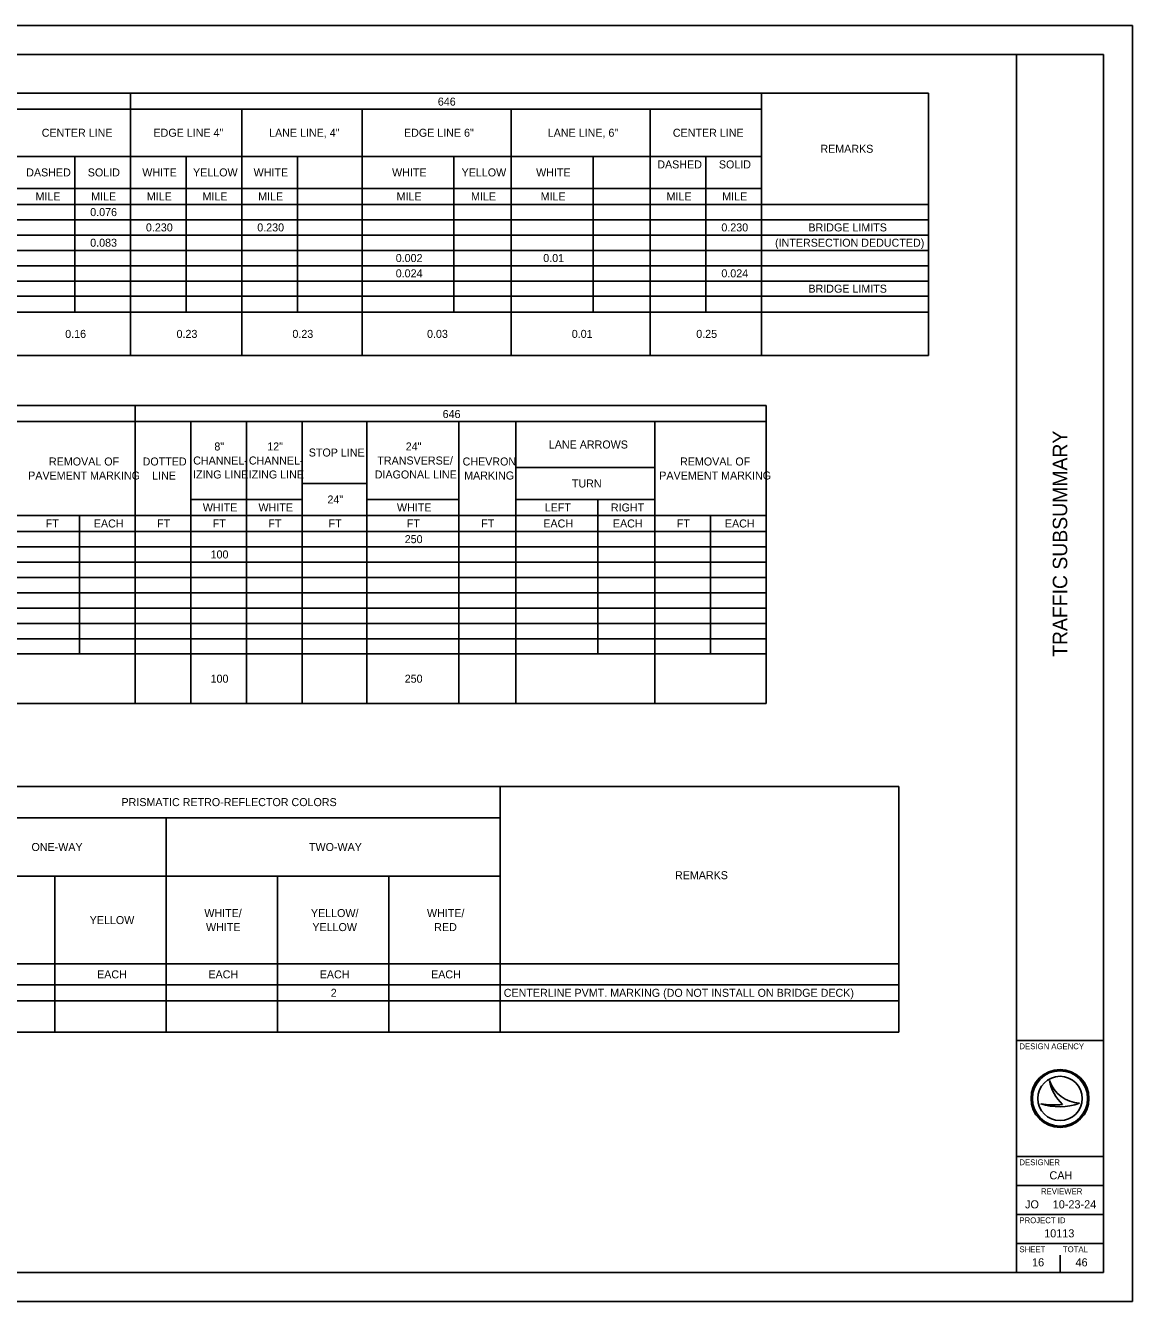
# Model space of a CAD drawing. Extents: x 0 to 53.1, y -5.3 to 22.
# Drawn here: x 14.91 to 34, y 0 to 22 of the extents above; entities that cross this region are included whole.
import ezdxf

# ---------------------------------------------------------------- set-up
doc = ezdxf.new("R2010")
doc.units = 0
for name, color, linetype in [('SH_Border', 7, 'Continuous'), ('SH_Cut_Line', 7, 'Continuous'), ('SH_Data', 7, 'Continuous'), ('SH_Text', 7, 'Continuous')]:
    doc.layers.add(name, color=color, linetype=linetype)

msp = doc.modelspace()

# ---------------------------------------------------------------- linework, layer by layer
at = {"layer": 'SH_Border'}
for p, q in [((32, 0.5), (32, 21.5)), ((32, 4.5), (33.5, 4.5)), ((32, 2.5), (33.5, 2.5)), ((32, 2), (33.5, 2)), ((32, 1.5), (33.5, 1.5)), ((32, 1), (33.5, 1))]:
    msp.add_line(p, q, dxfattribs=at)
msp.add_lwpolyline([(1.5, 21.5), (33.5, 21.5), (33.5, 0.5), (1.5, 0.5)], close=True, dxfattribs=at)
at = {"layer": 'SH_Cut_Line'}
msp.add_lwpolyline([(0, 0), (34, 0), (34, 22), (0, 22)], close=True, dxfattribs=at)
at = {"layer": 'SH_Data'}
for p, q in [((32.567, 3.81), (32.567, 3.81)), ((32.417, 3.41), (32.417, 3.41)), ((32.75, 3.5), (32.75, 3.5)), ((33.087, 3.419), (33.087, 3.419)), ((32.375, 0.675), (32.375, 0.675)), ((32.75, 0.5), (32.75, 0.8))]:
    msp.add_line(p, q, dxfattribs=at)
for radius in [0.5, 0.477, 0.477, 0.382]:
    msp.add_circle((32.75, 3.5), radius, dxfattribs=at)
for centre, radius, start, end in [((33.116, 3.998), 0.58, 198.9257, 198.9319), ((33.347, 3.97), 0.796, 191.6379, 191.6421), ((33.116, 3.998), 0.58, 198.9319, 267.1657), ((33.347, 3.97), 0.796, 191.6421, 226.0947), ((32.739, 4.37), 1.013, 251.4576, 290.0832), ((32.648, 4.654), 1.266, 259.4964, 259.4995), ((32.739, 4.37), 1.013, 251.4527, 251.4576), ((32.648, 4.654), 1.266, 259.4995, 276.6672)]:
    msp.add_arc(centre, radius, start, end, dxfattribs=at)
at = {"layer": 'SH_Text'}
for p, q in [((7.85, 20.835), (30.482, 20.835)), ((16.718, 20.835), (16.718, 20.559)), ((27.602, 20.835), (27.602, 20.019)), ((30.482, 20.835), (30.482, 20.019)), ((10.034, 20.559), (27.602, 20.559)), ((16.718, 20.559), (16.718, 20.019)), ((18.638, 20.559), (18.638, 20.019)), ((20.714, 20.559), (20.714, 20.019)), ((23.282, 20.559), (23.282, 20.019)), ((25.682, 20.559), (25.682, 20.019)), ((16.718, 20.019), (16.718, 19.467)), ((18.638, 20.019), (18.638, 19.743)), ((20.714, 20.019), (20.714, 19.467)), ((23.282, 20.019), (23.282, 19.743)), ((25.682, 20.019), (25.682, 19.467)), ((27.602, 20.019), (27.602, 19.467)), ((30.482, 20.019), (30.482, 19.467)), ((10.034, 19.743), (27.602, 19.743)), ((15.758, 19.743), (15.758, 19.467)), ((17.678, 19.743), (17.678, 19.467)), ((18.638, 19.743), (18.638, 19.467)), ((19.598, 19.743), (19.598, 19.467)), ((22.298, 19.743), (22.298, 19.467)), ((23.282, 19.743), (23.282, 19.467)), ((24.698, 19.743), (24.698, 19.467)), ((26.642, 19.743), (26.642, 19.467)), ((15.758, 19.467), (15.758, 19.191)), ((16.718, 19.467), (16.718, 19.191)), ((17.678, 19.467), (17.678, 19.191)), ((18.638, 19.467), (18.638, 19.191)), ((19.598, 19.467), (19.598, 19.191)), ((20.714, 19.467), (20.714, 19.191)), ((22.298, 19.467), (22.298, 19.191)), ((23.282, 19.467), (23.282, 19.191)), ((24.698, 19.467), (24.698, 19.191)), ((25.682, 19.467), (25.682, 19.191)), ((26.642, 19.467), (26.642, 19.191)), ((27.602, 19.467), (27.602, 19.191)), ((30.482, 19.467), (30.482, 19.191)), ((7.85, 19.191), (27.602, 19.191)), ((15.758, 19.191), (15.758, 17.859)), ((16.718, 19.191), (16.718, 17.859)), ((17.678, 19.191), (17.678, 17.859)), ((18.638, 19.191), (18.638, 17.859)), ((19.598, 19.191), (19.598, 17.859)), ((20.714, 19.191), (20.714, 17.859)), ((22.298, 19.191), (22.298, 17.859)), ((23.282, 19.191), (23.282, 17.859)), ((24.698, 19.191), (24.698, 17.859)), ((25.682, 19.191), (25.682, 17.859)), ((26.642, 19.191), (26.642, 17.859)), ((27.602, 19.191), (27.602, 17.859)), ((30.482, 19.191), (30.482, 17.859)), ((7.85, 18.915), (30.482, 18.915)), ((7.85, 18.651), (30.482, 18.651)), ((7.85, 18.387), (30.482, 18.387)), ((7.85, 18.123), (30.482, 18.123)), ((7.85, 17.859), (30.482, 17.859)), ((15.758, 17.859), (15.758, 17.595)), ((16.718, 17.859), (16.718, 17.595)), ((17.678, 17.859), (17.678, 17.595)), ((18.638, 17.859), (18.638, 17.595)), ((19.598, 17.859), (19.598, 17.595)), ((20.714, 17.859), (20.714, 17.595)), ((22.298, 17.859), (22.298, 17.595)), ((23.282, 17.859), (23.282, 17.595)), ((24.698, 17.859), (24.698, 17.595)), ((25.682, 17.859), (25.682, 17.595)), ((26.642, 17.859), (26.642, 17.595)), ((27.602, 17.859), (27.602, 17.595)), ((30.482, 17.859), (30.482, 17.595)), ((7.85, 17.595), (30.482, 17.595)), ((15.758, 17.595), (15.758, 17.055)), ((16.718, 17.595), (16.718, 16.311)), ((17.678, 17.595), (17.678, 17.055)), ((18.638, 17.595), (18.638, 16.311)), ((19.598, 17.595), (19.598, 17.055)), ((20.714, 17.595), (20.714, 16.311)), ((22.298, 17.595), (22.298, 17.055)), ((23.282, 17.595), (23.282, 16.311)), ((24.698, 17.595), (24.698, 17.055)), ((25.682, 17.595), (25.682, 16.311)), ((26.642, 17.595), (26.642, 17.055)), ((27.602, 17.595), (27.602, 16.311)), ((30.482, 17.595), (30.482, 16.311)), ((7.85, 17.331), (30.482, 17.331)), ((7.85, 17.055), (30.482, 17.055)), ((7.85, 16.311), (30.482, 16.311)), ((7.933, 15.448), (27.685, 15.448)), ((16.801, 15.448), (16.801, 15.172)), ((27.685, 15.448), (27.685, 15.172)), ((7.933, 15.172), (27.685, 15.172)), ((16.801, 15.172), (16.801, 14.656)), ((17.761, 15.172), (17.761, 14.656)), ((18.721, 15.172), (18.721, 14.656)), ((19.681, 15.172), (19.681, 14.656)), ((20.797, 15.172), (20.797, 14.656)), ((22.381, 15.172), (22.381, 14.656)), ((23.365, 15.172), (23.365, 14.656)), ((25.765, 15.172), (25.765, 14.656)), ((27.685, 15.172), (27.685, 14.656)), ((16.801, 14.656), (16.801, 14.38)), ((17.761, 14.656), (17.761, 14.38)), ((18.721, 14.656), (18.721, 14.38)), ((19.681, 14.656), (19.681, 14.38)), ((20.797, 14.656), (20.797, 14.38)), ((22.381, 14.656), (22.381, 14.38)), ((23.365, 14.656), (23.365, 14.38)), ((25.765, 14.656), (25.765, 14.38)), ((27.685, 14.656), (27.685, 14.38)), ((16.801, 14.38), (16.801, 14.104)), ((17.761, 14.38), (17.761, 14.104)), ((18.721, 14.38), (18.721, 14.104)), ((19.681, 14.38), (19.681, 14.104)), ((20.797, 14.38), (20.797, 14.104)), ((22.381, 14.38), (22.381, 14.104)), ((23.365, 14.38), (25.765, 14.38)), ((23.365, 14.38), (23.365, 14.104)), ((25.765, 14.38), (25.765, 14.104)), ((27.685, 14.38), (27.685, 14.104)), ((16.801, 14.104), (16.801, 13.828)), ((17.761, 14.104), (17.761, 13.828)), ((18.721, 14.104), (18.721, 13.828)), ((19.681, 14.104), (20.797, 14.104)), ((19.681, 14.104), (19.681, 13.828)), ((20.797, 14.104), (20.797, 13.828)), ((22.381, 14.104), (22.381, 13.828)), ((23.365, 14.104), (23.365, 13.828)), ((25.765, 14.104), (25.765, 13.828)), ((27.685, 14.104), (27.685, 13.828)), ((16.801, 13.828), (16.801, 13.552)), ((17.761, 13.828), (19.681, 13.828)), ((17.761, 13.828), (17.761, 13.552)), ((18.721, 13.828), (18.721, 13.552)), ((19.681, 13.828), (19.681, 13.552)), ((20.797, 13.828), (22.381, 13.828)), ((20.797, 13.828), (20.797, 13.552)), ((22.381, 13.828), (22.381, 13.552)), ((23.365, 13.828), (25.765, 13.828)), ((23.365, 13.828), (23.365, 13.552)), ((24.781, 13.828), (24.781, 13.552)), ((25.765, 13.828), (25.765, 13.552)), ((27.685, 13.828), (27.685, 13.552)), ((7.933, 13.552), (27.685, 13.552)), ((15.841, 13.552), (15.841, 12.748)), ((16.801, 13.552), (16.801, 12.748)), ((17.761, 13.552), (17.761, 12.748)), ((18.721, 13.552), (18.721, 12.748)), ((19.681, 13.552), (19.681, 12.748)), ((20.797, 13.552), (20.797, 12.748)), ((22.381, 13.552), (22.381, 12.748)), ((23.365, 13.552), (23.365, 12.748)), ((24.781, 13.552), (24.781, 12.748)), ((25.765, 13.552), (25.765, 12.748)), ((26.725, 13.552), (26.725, 12.748)), ((27.685, 13.552), (27.685, 12.748)), ((7.933, 13.276), (27.685, 13.276)), ((7.933, 13.012), (27.685, 13.012)), ((7.933, 12.748), (27.685, 12.748)), ((15.841, 12.748), (15.841, 12.484)), ((16.801, 12.748), (16.801, 12.484)), ((17.761, 12.748), (17.761, 12.484)), ((18.721, 12.748), (18.721, 12.484)), ((19.681, 12.748), (19.681, 12.484)), ((20.797, 12.748), (20.797, 12.484)), ((22.381, 12.748), (22.381, 12.484)), ((23.365, 12.748), (23.365, 12.484)), ((24.781, 12.748), (24.781, 12.484)), ((25.765, 12.748), (25.765, 12.484)), ((26.725, 12.748), (26.725, 12.484)), ((27.685, 12.748), (27.685, 12.484)), ((7.933, 12.484), (27.685, 12.484)), ((15.841, 12.484), (15.841, 12.22)), ((16.801, 12.484), (16.801, 12.22)), ((17.761, 12.484), (17.761, 12.22)), ((18.721, 12.484), (18.721, 12.22)), ((19.681, 12.484), (19.681, 12.22)), ((20.797, 12.484), (20.797, 12.22)), ((22.381, 12.484), (22.381, 12.22)), ((23.365, 12.484), (23.365, 12.22)), ((24.781, 12.484), (24.781, 12.22)), ((25.765, 12.484), (25.765, 12.22)), ((26.725, 12.484), (26.725, 12.22)), ((27.685, 12.484), (27.685, 12.22)), ((7.933, 12.22), (27.685, 12.22)), ((15.841, 12.22), (15.841, 11.956)), ((16.801, 12.22), (16.801, 11.956)), ((17.761, 12.22), (17.761, 11.956)), ((18.721, 12.22), (18.721, 11.956)), ((19.681, 12.22), (19.681, 11.956)), ((20.797, 12.22), (20.797, 11.956)), ((22.381, 12.22), (22.381, 11.956)), ((23.365, 12.22), (23.365, 11.956)), ((24.781, 12.22), (24.781, 11.956)), ((25.765, 12.22), (25.765, 11.956)), ((26.725, 12.22), (26.725, 11.956)), ((27.685, 12.22), (27.685, 11.956)), ((7.933, 11.956), (27.685, 11.956)), ((15.841, 11.956), (15.841, 11.164)), ((16.801, 11.956), (16.801, 10.312)), ((17.761, 11.956), (17.761, 10.312)), ((18.721, 11.956), (18.721, 10.312)), ((19.681, 11.956), (19.681, 10.312)), ((20.797, 11.956), (20.797, 10.312)), ((22.381, 11.956), (22.381, 10.312)), ((23.365, 11.956), (23.365, 10.312)), ((24.781, 11.956), (24.781, 11.164)), ((25.765, 11.956), (25.765, 10.312)), ((26.725, 11.956), (26.725, 11.164)), ((27.685, 11.956), (27.685, 10.312)), ((7.933, 11.692), (27.685, 11.692)), ((7.933, 11.428), (27.685, 11.428)), ((7.933, 11.164), (27.685, 11.164)), ((7.933, 10.312), (27.685, 10.312)), ((1.857, 8.88), (29.973, 8.88)), ((23.097, 8.88), (23.097, 7.332)), ((29.973, 8.88), (29.973, 7.332)), ((29.973, 8.88), (29.973, 4.644)), ((13.497, 8.34), (23.097, 8.34)), ((17.337, 8.34), (17.337, 7.332)), ((13.497, 7.332), (23.097, 7.332)), ((15.417, 7.332), (15.417, 4.644)), ((17.337, 7.332), (17.337, 4.644)), ((19.257, 7.332), (19.257, 4.644)), ((21.177, 7.332), (21.177, 4.644)), ((23.097, 7.332), (23.097, 4.644)), ((29.973, 7.332), (29.973, 4.644)), ((11.577, 5.82), (29.973, 5.82)), ((1.857, 5.46), (29.973, 5.46)), ((1.857, 5.184), (29.973, 5.184)), ((1.857, 4.644), (29.973, 4.644))]:
    msp.add_line(p, q, dxfattribs=at)

# ---------------------------------------------------------------- texts
at = {"layer": 'SH_Data'}
msp.add_text('TRAFFIC SUBSUMMARY', height=0.25, rotation=90, dxfattribs=at).set_placement((32.875, 11.114))
for s, height, p in [('DESIGN AGENCY', 0.1, (32.05, 4.35)), ('DESIGNER', 0.1, (32.05, 2.35)), ('CAH', 0.14, (32.568, 2.105)), ('REVIEWER', 0.1, (32.422, 1.85)), ('JO', 0.14, (32.147, 1.605)), ('10-23-24', 0.14, (32.625, 1.605)), ('PROJECT ID', 0.1, (32.05, 1.35)), ('10113', 0.14, (32.477, 1.105)), ('SHEET', 0.1, (32.05, 0.85)), ('TOTAL', 0.1, (32.8, 0.85)), ('16', 0.14, (32.268, 0.605)), ('46', 0.14, (33.018, 0.605))]:
    msp.add_text(s, height=height, dxfattribs=at).set_placement(p)
at = {"layer": 'SH_Text'}
for s, p in [('646', (22.02, 20.619)), ('CENTER LINE', (15.189, 20.082)), ('EDGE LINE 4"', (17.116, 20.082)), ('LANE LINE, 4"', (19.11, 20.082)), ('EDGE LINE 6"', (21.436, 20.082)), ('LANE LINE, 6"', (23.916, 20.082)), ('CENTER LINE', (26.073, 20.082)), ('REMARKS', (28.618, 19.806)), ('DASHED', (25.805, 19.536)), ('SOLID', (26.867, 19.536)), ('DASHED', (14.921, 19.398)), ('SOLID', (15.983, 19.398)), ('WHITE', (16.923, 19.398)), ('YELLOW', (17.798, 19.398)), ('WHITE', (18.843, 19.398)), ('WHITE', (21.231, 19.398)), ('YELLOW', (22.43, 19.398)), ('WHITE', (23.715, 19.398)), ('MILE', (15.081, 18.984)), ('MILE', (16.041, 18.984)), ('MILE', (17.001, 18.984)), ('MILE', (17.961, 18.984)), ('MILE', (18.921, 18.984)), ('MILE', (21.309, 18.984)), ('MILE', (22.593, 18.984)), ('MILE', (23.793, 18.984)), ('MILE', (25.965, 18.984)), ('MILE', (26.925, 18.984)), ('0.076', (16.025, 18.714)), ('0.230', (16.986, 18.45)), ('0.230', (18.906, 18.45)), ('0.230', (26.91, 18.45)), ('BRIDGE LIMITS', (28.411, 18.45)), ('0.083', (16.025, 18.186)), ('(INTERSECTION DEDUCTED)', (27.836, 18.186)), ('0.002', (21.294, 17.922)), ('0.01', (23.838, 17.922)), ('0.024', (21.294, 17.658)), ('0.024', (26.91, 17.658)), ('BRIDGE LIMITS', (28.411, 17.394)), ('0.16', (15.594, 16.614)), ('0.23', (17.514, 16.614)), ('0.23', (19.512, 16.614)), ('0.03', (21.834, 16.614)), ('0.01', (24.33, 16.614)), ('0.25', (26.477, 16.614)), ('646', (22.103, 15.232)), ('8"', (18.166, 14.673)), ('12"', (19.078, 14.673)), ('24" ', (21.466, 14.673)), ('LANE ARROWS', (23.934, 14.707)), (' REMOVAL OF ', (15.262, 14.414)), ('DOTTED ', (16.929, 14.414)), ('CHANNEL-', (17.801, 14.431)), ('CHANNEL-', (18.761, 14.431)), ('STOP LINE', (19.794, 14.569)), ('TRANSVERSE/ ', (20.977, 14.431)), ('CHEVRON ', (22.447, 14.414)), (' REMOVAL OF ', (26.146, 14.414)), ('PAVEMENT MARKING', (14.955, 14.172)), ('LINE', (17.093, 14.172)), ('IZING LINE', (17.798, 14.19)), ('IZING LINE', (18.758, 14.19)), ('DIAGONAL LINE', (20.932, 14.19)), ('MARKING', (22.474, 14.172)), ('PAVEMENT MARKING', (25.839, 14.172)), ('TURN', (24.332, 14.035)), ('24"', (20.116, 13.759)), ('WHITE', (17.967, 13.621)), ('WHITE', (18.927, 13.621)), ('WHITE', (21.315, 13.621)), ('LEFT', (23.863, 13.621)), ('RIGHT', (25.005, 13.621)), ('FT', (15.257, 13.345)), ('EACH', (16.087, 13.345)), ('FT', (17.177, 13.345)), ('FT', (18.137, 13.345)), ('FT', (19.097, 13.345)), ('FT', (20.135, 13.345)), ('FT', (21.485, 13.345)), ('FT', (22.769, 13.345)), ('EACH', (23.839, 13.345)), ('EACH', (25.039, 13.345)), ('FT', (26.141, 13.345)), ('EACH', (26.971, 13.345)), ('250', (21.449, 13.075)), ('100', (18.101, 12.811)), ('100', (18.101, 10.669)), ('250', (21.449, 10.669)), ('PRISMATIC RETRO-REFLECTOR COLORS', (16.564, 8.541)), ('ONE-WAY', (15.012, 7.767)), ('TWO-WAY', (19.798, 7.767)), ('REMARKS', (26.11, 7.281)), ('YELLOW', (16.016, 6.507)), ('WHITE/', (17.993, 6.628)), ('YELLOW/', (19.831, 6.628)), ('WHITE/', (21.833, 6.628)), ('WHITE', (18.022, 6.386)), ('YELLOW', (19.856, 6.386)), ('RED', (21.958, 6.386)), ('EACH', (16.143, 5.571)), ('EACH', (18.063, 5.571)), ('EACH', (19.983, 5.571)), ('EACH', (21.903, 5.571)), ('2', (20.173, 5.253)), ('CENTERLINE PVMT. MARKING (DO NOT INSTALL ON BRIDGE DECK)', (23.157, 5.253))]:
    msp.add_text(s, height=0.138, dxfattribs=at).set_placement(p)

doc.saveas('drawing.dxf')
